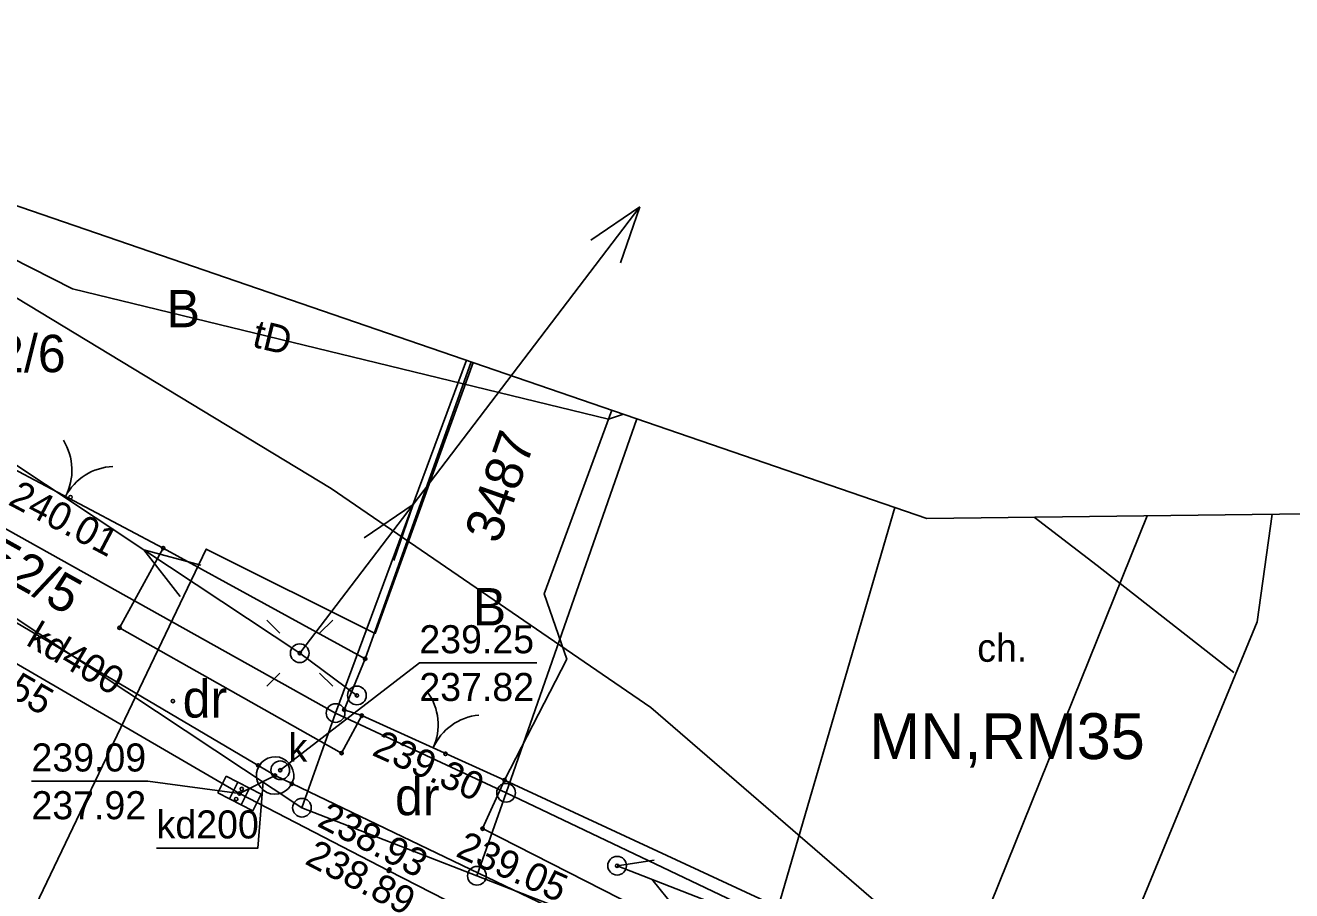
# Model space of a CAD drawing. Extents: x 6596400 to 6597200, y 5539751 to 5540251.
# Drawn here: x 6596673.62 to 6596707.49, y 5540110.79 to 5540133.92 of the extents above; entities that cross this region are included whole.
import ezdxf

# ---------------------------------------------------------------- set-up
doc = ezdxf.new("R2010")
doc.units = 0
for name, color, linetype in [('140-Punkty robocze', 7, 'Continuous'), ('202-punkt graniczny', 7, 'Continuous'), ('210-oznaczenie konturu użytku gruntowego', 7, 'Continuous'), ('211-numer działki ewidencyjnej', 7, 'Continuous'), ('218-kontur użytku gruntowego', 7, 'Continuous'), ('219-działka ewidencyjna', 7, 'Continuous'), ('brama', 7, 'Continuous'), ('chodnik', 7, 'Continuous'), ('chodnik-Atr17', 7, 'Continuous'), ('jezdnia', 7, 'Continuous'), ('komora podziemna', 7, 'Continuous'), ('kratka ściekowa', 7, 'Continuous'), ('krawężnik', 7, 'Continuous'), ('latarnia', 7, 'Continuous'), ('Linia obszaru zagospodarowania terenu', 7, 'Continuous'), ('Nieprzekraczalna linia zabudowy', 7, 'Continuous'), ('ogrodzenie trwałe', 7, 'Continuous'), ('Opis obszaru zagospodarowania terenu', 7, 'Continuous'), ('pikieta sztuczna', 7, 'Continuous'), ('pikieta sztuczna-Atr2', 7, 'Continuous'), ('przewód elektroenergetyczny niskiego napięcia', 7, 'Continuous'), ('przewód elektroenergetyczny podziemny', 7, 'Continuous'), ('przewód kanalizacyjny', 7, 'Continuous'), ('przewód kanalizacyjny-Atr1', 7, 'Continuous'), ('przewód telekomunikacyjny napowietrzny', 7, 'Continuous'), ('przewód telekomunikacyjny podziemny', 7, 'Continuous'), ('przewód telekomunikacyjny podziemny-Atr1', 7, 'Continuous'), ('rzedna', 7, 'Continuous'), ('rzedna-Atr2', 7, 'Continuous'), ('rzedna-Atr3', 7, 'Continuous'), ('słup przewodów napowietrznych', 7, 'Continuous'), ('właz do komory lub kanału - okrągły', 7, 'Continuous'), ('właz do komory lub kanału - okrągły-Atr17', 7, 'Continuous'), ('Zakres', 7, 'Continuous')]:
    doc.layers.add(name, color=color, linetype=linetype)

# ---------------------------------------------------------------- blocks, each defined once
blk = doc.blocks.new('202')
blk.add_circle((0, 0), 0.25)
blk = doc.blocks.new('SUTP')
for p, q in [((0, 0), (0.866, 0.5)), ((9.232, 0), (8.366, 0.5)), ((0, 0), (9.232, 0)), ((1.866, -0.5), (1, 0)), ((7.366, -0.5), (8.232, 0))]:
    blk.add_line(p, q)
blk = doc.blocks.new('OK02')
for centre, start, end in [((-1.5, 0), 0, 60), ((1.5, 0), 120, 180)]:
    blk.add_arc(centre, 1.5, start, end)
blk = doc.blocks.new('SM05')
blk.add_circle((0, 0), 0.25)
blk = doc.blocks.new('SUEP1')
for p, q in [((5, 0), (3.5, 0.5)), ((15, 0), (13.5, 0.5)), ((0, 0), (5, 0)), ((5, 0), (3.5, -0.5)), ((5, 0), (15, 0)), ((15, 0), (13.5, -0.5))]:
    blk.add_line(p, q)
blk = doc.blocks.new('SM01')
for p, q in [((-0.53, 0.531), (-0.883, 0.884)), ((0.531, 0.531), (0.884, 0.884)), ((-0.53, -0.53), (-0.883, -0.883)), ((0.531, -0.53), (0.884, -0.883))]:
    blk.add_line(p, q)
blk.add_circle((0, 0), 0.25)
blk = doc.blocks.new('US15')
blk.add_circle((0, 0), 0.25)
blk = doc.blocks.new('US05')
for p, q in [((-0.525, -0.25), (-0.525, 0.25)), ((-0.525, 0.25), (-0.175, 0.25)), ((-0.175, -0.25), (-0.175, 0.25)), ((-0.175, 0.25), (0.175, 0.25)), ((0.175, -0.25), (0.175, 0.25)), ((0.175, 0.25), (0.525, 0.25)), ((0.525, -0.25), (0.525, 0.25)), ((-0.525, -0.25), (-0.175, -0.25)), ((-0.175, -0.25), (0.175, -0.25)), ((0.175, -0.25), (0.525, -0.25))]:
    blk.add_line(p, q)
blk = doc.blocks.new('US22')
blk.add_circle((0, 0), 0.25)
blk = doc.blocks.new('PW01')
blk.add_circle((0, 0), 0.045)
blk = doc.blocks.new('PIKIETA')
blk.add_circle((0, 0), 0.045)

msp = doc.modelspace()

# ---------------------------------------------------------------- linework, layer by layer
at = {"layer": '218-kontur użytku gruntowego'}
for points in [[(6596681.92, 5540115.54), (6596662.85, 5540126.18)], [(6596662.85, 5540126.18), (6596681.92, 5540115.54)], [(6596663.08, 5540124.88), (6596681.02, 5540113.01)], [(6596681.02, 5540113.01), (6596663.08, 5540124.88)], [(6596681.92, 5540115.54), (6596685.422, 5540124.967)], [(6596685.422, 5540124.967), (6596681.92, 5540115.54)], [(6596686.48, 5540113.41), (6596689.974, 5540123.403)], [(6596689.974, 5540123.403), (6596686.48, 5540113.41)], [(6596681.02, 5540113.01), (6596681.92, 5540115.54)], [(6596681.92, 5540115.54), (6596681.02, 5540113.01)], [(6596686.48, 5540113.41), (6596681.92, 5540115.54)], [(6596681.92, 5540115.54), (6596686.48, 5540113.41)], [(6596685.7, 5540111.19), (6596686.48, 5540113.41)], [(6596686.48, 5540113.41), (6596685.7, 5540111.19)], [(6596714.65, 5540099.99), (6596686.48, 5540113.41)], [(6596686.48, 5540113.41), (6596714.65, 5540099.99)], [(6596681.02, 5540113.01), (6596685.7, 5540111.19)], [(6596685.7, 5540111.19), (6596681.02, 5540113.01)], [(6596685.7, 5540111.19), (6596696.79, 5540106.87)], [(6596696.79, 5540106.87), (6596685.7, 5540111.19)]]:
    msp.add_lwpolyline(points, dxfattribs=at)
at = {"layer": '219-działka ewidencyjna'}
for points in [[(6596681.92, 5540115.54), (6596662.85, 5540126.18)], [(6596681.02, 5540113.01), (6596663.08, 5540124.88)], [(6596681.92, 5540115.54), (6596685.422, 5540124.967)], [(6596686.48, 5540113.41), (6596689.974, 5540123.403)], [(6596681.02, 5540113.01), (6596681.92, 5540115.54)], [(6596685.7, 5540111.19), (6596686.48, 5540113.41)], [(6596681.02, 5540113.01), (6596685.7, 5540111.19)], [(6596696.79, 5540106.87), (6596685.7, 5540111.19)]]:
    msp.add_lwpolyline(points, dxfattribs=at)
at = {"layer": 'brama'}
for points in [[(6596672.08, 5540122.71), (6596677.31, 5540119.95)], [(6596682.62, 5540115.47), (6596686.44, 5540113.75)]]:
    msp.add_lwpolyline(points, dxfattribs=at)
at = {"layer": 'chodnik'}
for points in [[(6596672.08, 5540122.71), (6596677.31, 5540119.95), (6596676.14, 5540117.82), (6596682.08, 5540114.47), (6596682.62, 5540115.47), (6596686.44, 5540113.75), (6596685.85, 5540112.45), (6596693.18, 5540108.72), (6596693.76, 5540110.35), (6596698.55, 5540108.24), (6596697.87, 5540106.5), (6596705.5, 5540103.32), (6596709.65, 5540101.73), (6596713.73, 5540100.03), (6596712.8, 5540098.2), (6596708.8, 5540099.55), (6596704.7, 5540101.24), (6596694.34, 5540105.7), (6596683.34, 5540111.32), (6596679.35, 5540113.39), (6596672.62, 5540117.3)], [(6596696.877, 5540121.033), (6596693.76, 5540110.35), (6596698.55, 5540108.24), (6596703.628, 5540120.812)]]:
    msp.add_lwpolyline(points, dxfattribs=at)
at = {"layer": 'jezdnia'}
for points in [[(6596728.26, 5540094.5), (6596723.35, 5540095.14), (6596720.92, 5540095.72), (6596718.03, 5540096.54), (6596712.8, 5540098.2), (6596708.8, 5540099.55), (6596704.7, 5540101.24), (6596694.34, 5540105.7), (6596683.34, 5540111.32), (6596679.35, 5540113.39), (6596672.62, 5540117.3), (6596666.82, 5540120.65), (6596657.79, 5540125.88), (6596655.967, 5540126.802)], [(6596685.549, 5540124.923), (6596682.71, 5540116.99), (6596682.15, 5540115.63), (6596682.62, 5540115.47), (6596686.44, 5540113.75), (6596688.1, 5540116.98), (6596687.5, 5540118.73), (6596689.31, 5540123.632)]]:
    msp.add_lwpolyline(points, dxfattribs=at)
at = {"layer": 'komora podziemna'}
msp.add_lwpolyline([(6596679.92, 5540113.55), (6596679.99, 5540113.48), (6596680.08, 5540113.42), (6596680.18, 5540113.38), (6596680.28, 5540113.37), (6596680.39, 5540113.38), (6596680.49, 5540113.41), (6596680.58, 5540113.46), (6596680.66, 5540113.52), (6596680.72, 5540113.61), (6596680.77, 5540113.7), (6596680.8, 5540113.8), (6596680.8, 5540113.91), (6596680.78, 5540114.01), (6596680.74, 5540114.1), (6596680.68, 5540114.19), (6596680.61, 5540114.26), (6596680.52, 5540114.32), (6596680.42, 5540114.36), (6596680.32, 5540114.37), (6596680.21, 5540114.36), (6596680.11, 5540114.33), (6596680.02, 5540114.28), (6596679.94, 5540114.22), (6596679.88, 5540114.13), (6596679.83, 5540114.04), (6596679.8, 5540113.94), (6596679.8, 5540113.83), (6596679.82, 5540113.73), (6596679.86, 5540113.64)], close=True, dxfattribs=at)
at = {"layer": 'krawężnik'}
msp.add_lwpolyline([(6596712.8, 5540098.2), (6596708.8, 5540099.55), (6596704.7, 5540101.24), (6596694.34, 5540105.7), (6596683.34, 5540111.32), (6596679.35, 5540113.39), (6596672.62, 5540117.3), (6596666.82, 5540120.65), (6596657.79, 5540125.88), (6596655.967, 5540126.802)], dxfattribs=at)
at = {"layer": 'Linia obszaru zagospodarowania terenu'}
for points in [[(6596664.616, 5540132.112), (6596671.21, 5540127.95), (6596681.8, 5540121.54), (6596690.35, 5540115.69), (6596701.61, 5540105.97), (6596709.34, 5540098.61), (6596715.39, 5540091.82), (6596718.63, 5540088.53), (6596721.87, 5540084.71), (6596726.1, 5540083.21), (6596730.7, 5540082.79), (6596730.91, 5540075), (6596745.51, 5540074.64), (6596746.77, 5540082.74), (6596765.15, 5540085.09), (6596776.62, 5540086.27), (6596789.34, 5540086.1), (6596798.37, 5540085.54), (6596805.65, 5540083.56), (6596813.11, 5540081.53), (6596819.41, 5540077.54), (6596826.58, 5540072.81), (6596832.721, 5540067.998)], [(6596706.97, 5540120.853), (6596706.57, 5540117.98), (6596701.61, 5540105.97)]]:
    msp.add_lwpolyline(points, dxfattribs=at)
at = {"layer": 'Nieprzekraczalna linia zabudowy'}
msp.add_lwpolyline([(6596705.94, 5540116.62), (6596702.29, 5540119.48), (6596700.606, 5540120.775)], dxfattribs=at)
at = {"layer": 'ogrodzenie trwałe'}
for points in [[(6596685.549, 5540124.923), (6596682.71, 5540116.99), (6596682.15, 5540115.63), (6596682.62, 5540115.47)], [(6596677.31, 5540119.95), (6596682.71, 5540116.99)], [(6596686.44, 5540113.75), (6596693.76, 5540110.35)]]:
    msp.add_lwpolyline(points, dxfattribs=at)
at = {"layer": 'przewód elektroenergetyczny podziemny'}
msp.add_lwpolyline([(6596685.598, 5540124.906), (6596682.98, 5540117.67), (6596678.46, 5540119.92), (6596672.31, 5540107.09), (6596661.92, 5540104.4), (6596656.89, 5540108.44), (6596653.516, 5540105.493)], dxfattribs=at)
at = {"layer": 'przewód kanalizacyjny'}
for points in [[(6596652.409, 5540119.314), (6596659.51, 5540115.47), (6596667.73, 5540121.28), (6596680.3, 5540113.87), (6596707.99, 5540100.58), (6596711.34, 5540100.47), (6596715.95, 5540100.45)], [(6596680.3, 5540113.87), (6596679.35, 5540113.39)]]:
    msp.add_lwpolyline(points, dxfattribs=at)
at = {"layer": 'przewód kanalizacyjny-Atr1'}
msp.add_lwpolyline([(6596679.98, 5540113.71), (6596679.84, 5540111.93), (6596677.133, 5540111.93)], dxfattribs=at)
at = {"layer": 'przewód telekomunikacyjny podziemny'}
msp.add_lwpolyline([(6596689.623, 5540123.524), (6596689.22, 5540123.39), (6596674.88, 5540126.88), (6596664.474, 5540132.16)], dxfattribs=at)
at = {"layer": 'rzedna-Atr2'}
for points in [[(6596680.44, 5540114.01), (6596684.16, 5540116.88), (6596687.306, 5540116.88)], [(6596679.35, 5540113.39), (6596676.9, 5540113.72), (6596673.786, 5540113.72)]]:
    msp.add_lwpolyline(points, dxfattribs=at)
at = {"layer": 'słup przewodów napowietrznych'}
msp.add_lwpolyline([(6596682.49, 5540116.01), (6596680.96, 5540117.14)], dxfattribs=at)
at = {"layer": 'Zakres'}
msp.add_lwpolyline([(6596822.22, 5540097.5), (6596800.39, 5540105.4), (6596755.76, 5540121.45), (6596697.73, 5540120.74), (6596659.35, 5540133.92), (6596647.64, 5540109.28), (6596697.73, 5540077), (6596721.01, 5540057.77), (6596727.72, 5540045.95), (6596731.95, 5540033.61), (6596741.17, 5540031.18), (6596755.59, 5540029.2), (6596757.85, 5540044.22), (6596787.25, 5540055.04), (6596806.3, 5540048.33), (6596813.97, 5540042.6), (6596833.15, 5540068.58), (6596822.3, 5540077.75)], close=True, dxfattribs=at)

# ---------------------------------------------------------------- block references
at = {"layer": '140-Punkty robocze'}
for p in [(6596677.31, 5540119.95), (6596676.14, 5540117.82), (6596680.96, 5540117.14), (6596682.71, 5540116.99), (6596682.49, 5540116.01), (6596677.57, 5540115.86), (6596682.15, 5540115.63), (6596682.62, 5540115.47), (6596682.08, 5540114.47), (6596679.85, 5540114.14), (6596680.44, 5540114.01), (6596680.3, 5540113.87), (6596680.75, 5540113.65), (6596686.44, 5540113.75), (6596679.35, 5540113.39), (6596679.41, 5540113.51), (6596679.26, 5540113.24), (6596689.45, 5540111.46)]:
    msp.add_blockref('PIKIETA', p, dxfattribs=at)
at = {"layer": '202-punkt graniczny'}
for p in [(6596681.92, 5540115.54), (6596686.48, 5540113.41), (6596681.02, 5540113.01), (6596685.7, 5540111.19)]:
    msp.add_blockref('202', p, dxfattribs=at)
at = {"layer": 'brama'}
for p, rotation in [((6596674.695, 5540121.33), -27.82199999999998), ((6596684.53, 5540114.61), -24.24000000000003)]:
    msp.add_blockref('OK02', p, dxfattribs=dict(at, rotation=rotation))
at = {"layer": 'kratka ściekowa', "rotation": -26.927999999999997}
msp.add_blockref('US05', (6596679.35, 5540113.39), dxfattribs=at)
at = {"layer": 'latarnia'}
msp.add_blockref('SM01', (6596680.96, 5540117.14), dxfattribs=at)
at = {"layer": 'pikieta sztuczna'}
for p in [(6596674.83, 5540121.31), (6596684.86, 5540114.45), (6596685.85, 5540112.45), (6596683.34, 5540111.32), (6596683.36, 5540111.36)]:
    msp.add_blockref('PW01', p, dxfattribs=at)
at = {"layer": 'przewód elektroenergetyczny niskiego napięcia'}
for rotation in [52.673, 146.444]:
    msp.add_blockref('SUEP1', (6596680.96, 5540117.14), dxfattribs=dict(at, rotation=rotation))
at = {"layer": 'przewód telekomunikacyjny napowietrzny', "rotation": -21.254999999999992}
msp.add_blockref('SUTP', (6596689.45, 5540111.46), dxfattribs=at)
at = {"layer": 'rzedna'}
for p in [(6596680.44, 5540114.01), (6596679.35, 5540113.39)]:
    msp.add_blockref('PW01', p, dxfattribs=at)
at = {"layer": 'słup przewodów napowietrznych'}
for name, p in [('SM05', (6596680.96, 5540117.14)), ('SM05', (6596682.49, 5540116.01)), ('US15', (6596689.45, 5540111.46))]:
    msp.add_blockref(name, p, dxfattribs=at)
at = {"layer": 'właz do komory lub kanału - okrągły'}
msp.add_blockref('US22', (6596680.44, 5540114.01), dxfattribs=at)

# ---------------------------------------------------------------- texts
at = {"layer": '210-oznaczenie konturu użytku gruntowego'}
for s, p in [('B', (6596677.4, 5540125.85)), ('B', (6596685.59, 5540117.88)), ('dr', (6596677.83, 5540115.42)), ('dr', (6596683.51, 5540112.81))]:
    msp.add_text(s, height=1, dxfattribs=at).set_placement(p)
at = {"layer": '211-numer działki ewidencyjnej'}
msp.add_text('2752/6', height=1, dxfattribs=at).set_placement((6596670.61, 5540124.65))
for s, rotation, p in [('3487', 70.729, (6596686.29, 5540120.03)), ('2752/5', 330.841, (6596671.18, 5540120.13))]:
    msp.add_text(s, height=1, rotation=rotation, dxfattribs=at).set_placement(p)
at = {"layer": 'chodnik-Atr17'}
msp.add_text('ch.', height=0.75, dxfattribs=at).set_placement((6596699.08, 5540116.91))
at = {"layer": 'Opis obszaru zagospodarowania terenu'}
msp.add_text('MN,RM35', height=1.225, dxfattribs=at).set_placement((6596696.19, 5540114.31))
at = {"layer": 'pikieta sztuczna-Atr2'}
for s, rotation, p in [('240.01', 332.178, (6596673.13, 5540121.127)), ('239.55', 329.99, (6596671.425, 5540116.991)), ('239.30', 335.76, (6596682.862, 5540114.426)), ('238.93', 332.58, (6596681.395, 5540112.534)), ('239.05', 335.76, (6596685.102, 5540111.726)), ('238.89', 332.58, (6596681.065, 5540111.524))]:
    msp.add_text(s, height=0.75, rotation=rotation, dxfattribs=at).set_placement(p)
at = {"layer": 'przewód kanalizacyjny-Atr1'}
msp.add_text('kd400', height=0.75, rotation=329.481, dxfattribs=at).set_placement((6596673.61, 5540117.377))
msp.add_text('kd200', height=0.75, dxfattribs=at).set_placement((6596677.133, 5540112.188))
at = {"layer": 'przewód telekomunikacyjny podziemny-Atr1'}
msp.add_text('tD', height=0.75, rotation=346.321, dxfattribs=at).set_placement((6596679.661, 5540125.336))
at = {"layer": 'rzedna-Atr2'}
for s, p in [('239.25', (6596684.16, 5540117.138)), ('239.09', (6596673.786, 5540113.978))]:
    msp.add_text(s, height=0.75, dxfattribs=at).set_placement(p)
at = {"layer": 'rzedna-Atr3'}
for s, p in [('237.82', (6596684.16, 5540115.862)), ('237.92', (6596673.786, 5540112.702))]:
    msp.add_text(s, height=0.75, dxfattribs=at).set_placement(p)
at = {"layer": 'właz do komory lub kanału - okrągły-Atr17'}
msp.add_text('k', height=0.75, dxfattribs=at).set_placement((6596680.66, 5540114.24))

doc.saveas('drawing.dxf')
